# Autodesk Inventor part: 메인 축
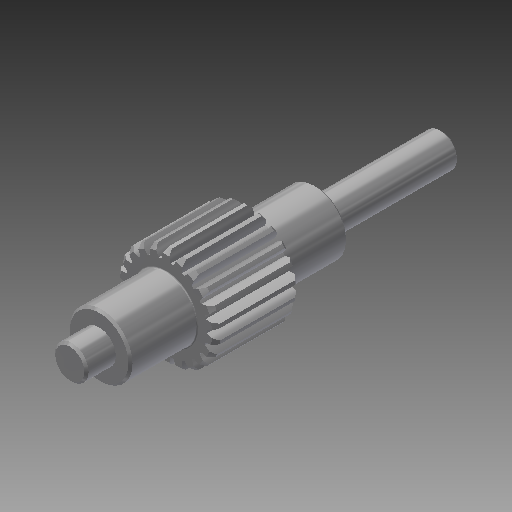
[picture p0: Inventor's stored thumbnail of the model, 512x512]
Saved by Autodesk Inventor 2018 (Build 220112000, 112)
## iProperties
Created: 2016-02
Part Number: 메인 축
Material: 강철, 연강
Document SubType Name: Modeling
Categories: <?xml version="1.0" encoding="UTF-16"?> <MemberInstance><Categories><FamilyTemplate><FamilyTemplateParameter ValueType="xs:double" Id="1" ObjectReferenceKey="da
Density: 7.86 g/cm^3
Appearance: 강철
CustomPartVersion: 1
Author: mdu
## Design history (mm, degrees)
sketch "Sketch1"
  geometry: C1 r 12 at (0, 0)
  constraints: 1 centre point
  dimensions: "d0" = 24 diameter of C1 (= da_da)
extrude "Extrusion1" new body sketch "Sketch1" distance "d1" = 20 (= da_b); taper "d2" = 0 deg
workplane "Work Plane2"
feature "피치 지름" dims "d4" = 10, "d5" = 0
workplane "Work Plane8"
workplane "Work Plane9"
chamfer "모따기1" distance "d49" = 1; stored, may be unused: second distance "d50" = 2, angle "d51" = 45 deg
sketch "스케치3"
  geometry: C1 r 7.5 at (0, 0); 1 further point
  constraints: 1 centre point, 1 coincident
  dimensions: "d52" = 15 diameter of C1
extrude "돌출2" join sketch "스케치3" distance "d53" = 16; taper "d54" = 0 deg
sketch "스케치4"
  geometry: C1 r 4 at (0, 0); 1 further point
  constraints: 1 centre point, 1 coincident
  dimensions: "d55" = 8 diameter of C1
extrude "돌출3" join sketch "스케치4" distance "d56" = 7; taper "d57" = 0 deg
sketch "스케치5"
  geometry: C1 r 7.5 at (0, 0) reference; C2 r 7.5 at (0, 0) reference; 1 further point
extrude "돌출4" join sketch "스케치5" distance "d62" = 16; taper "d63" = 0 deg
sketch "스케치6"
  geometry: C1 r 4 at (0, 0); 1 further point
  constraints: 1 centre point, 1 coincident
  dimensions: "d64" = 8 diameter of C1
extrude "돌출5" join sketch "스케치6" distance "d65" = 30; taper "d66" = 0 deg
chamfer "모따기2" distance "d58" = 0.5; stored, may be unused: second distance "d59" = 2, angle "d60" = 45 deg
fillet "모깎기1" dims "d61" = 0.3
feature "스퍼 기어" dims "da_b" = 20, "da_d" = 22, "da_aw" = 31, "da_da" = 24, "da_df" = 19.5, "da_dw" = 22, angle "da_beta" = 0 deg, "da_lefttooth" = 0, "da_righttooth" = 0
body "Solid1"
sketch "Sketch2"
  geometry: C1 r 12 at (0, 0) reference; C2 r 11 at (0, 0)
  constraints: 1 centre point, 1 coincident
  dimensions: "d3" = 22 diameter of C2 (= da_dw)
body "Srf1"
node "투영된 루프1"
other parameters: "d16" = 31 (= da_aw), "d17" = 0, "d34" = 1.428 (computed from da_z), "d39" = 0, "d41" = 0, "d43" = 31 (= da_aw), "d46" = 31 (= da_aw), "d47" = 0, "d48" = 0
